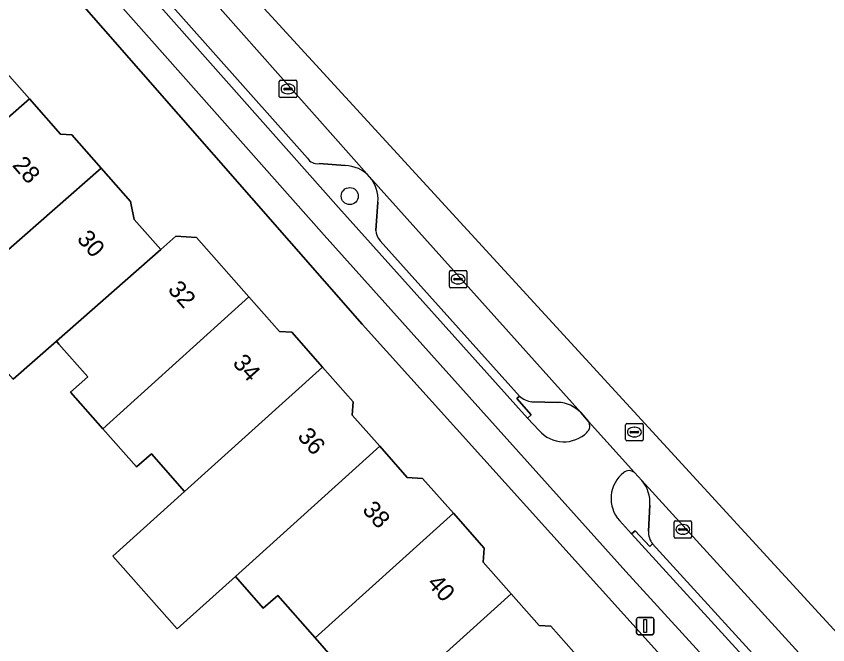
# Model space of a CAD drawing. Extents: x 159960 to 160866, y 382700 to 383354.
# Drawn here: x 160732.82 to 160779.46, y 383008.74 to 383044.85 of the extents above; entities that cross this region are included whole.
import ezdxf

# ---------------------------------------------------------------- set-up
doc = ezdxf.new("R2010")
doc.units = 0
for name, color, linetype in [('IMGEO_Berm_open', 7, 'Continuous'), ('IMGEO_Boom', 7, 'Continuous'), ('IMGEO_Erf', 7, 'Continuous'), ('IMGEO_Fietspad_gesloten', 7, 'Continuous'), ('IMGEO_Kolk', 7, 'Continuous'), ('IMGEO_Lichtmast', 7, 'Continuous'), ('IMGEO_Pand', 7, 'Continuous'), ('IMGEO_Pand_nummerreeks', 7, 'Continuous'), ('IMGEO_Parkeervlak_open', 7, 'Continuous'), ('IMGEO_Rijbaan_lokaal_gesloten', 7, 'Continuous'), ('IMGEO_Rioolput', 7, 'Continuous'), ('IMGEO_Verkeerseiland_gesloten', 7, 'Continuous'), ('IMGEO_Voetpad_open', 7, 'Continuous')]:
    doc.layers.add(name, color=color, linetype=linetype)

msp = doc.modelspace()

# ---------------------------------------------------------------- linework, layer by layer
at = {"layer": 'IMGEO_Berm_open'}
for points in [[(160700.875, 383094.511), (160700.804, 383094.591), (160698.59, 383096.925), (160695.704, 383099.8), (160694.16, 383101.338), (160689.088, 383106.239), (160687.38, 383107.889), (160684.6, 383110.794), (160683.967, 383110.175), (160686.696, 383107.388), (160688.818, 383104.989), (160694.352, 383098.361), (160701.018, 383090.565), (160751.341, 383033.866), (160762.195, 383021.758), (160762.421, 383021.957), (160761.588, 383022.894), (160761.747, 383023.027), (160753.731, 383031.938)], [(160749.55, 383036.695), (160733.605, 383054.628)], [(160751.719, 383036.276), (160750.222, 383036.377)], [(160753.486, 383032.54), (160753.608, 383034.161)], [(160777.531, 383005.612), (160769.389, 383014.532), (160769.234, 383014.393), (160768.396, 383015.285), (160768.171, 383015.103), (160799.663, 382980.632), (160799.88, 382980.845), (160798.069, 382982.871), (160798.218, 382983.015), (160781.941, 383000.79), (160781.708, 383001.508), (160781.754, 383002.991)]]:
    msp.add_lwpolyline(points, dxfattribs=at)
for centre, radius, start, end in [((160750.145, 383037.083), 0.71, 213.0951, 276.2565), ((160751.632, 383034.234), 2.044, 43.0411, 87.5688), ((160751.555, 383034.3), 2.058, 356.126, 40.228), ((160754.447, 383032.58), 0.962, 182.4046, 221.8858)]:
    msp.add_arc(centre, radius, start, end, dxfattribs=at)
at = {"layer": 'IMGEO_Boom'}
msp.add_circle((160751.985, 383034.517), 0.489, dxfattribs=at)
at = {"layer": 'IMGEO_Erf'}
for points in [[(160790.273, 382985.751), (160777.189, 383000), (160752.695, 383027.147), (160693.284, 383094.955), (160693.113, 383094.806), (160692.06, 383095.951)], [(160730.563, 383043.514), (160733.575, 383040.1), (160735.367, 383038.069), (160736.022, 383038.028), (160737.708, 383036.117), (160739.394, 383034.206), (160739.602, 383033.176), (160741.127, 383031.448), (160741.992, 383032.211), (160743.189, 383032.136), (160746.195, 383028.73), (160747.958, 383026.731), (160748.65, 383026.688), (160750.414, 383024.689), (160752.179, 383022.689), (160752.131, 383021.929), (160753.708, 383020.142), (160755.286, 383018.353), (160756.17, 383018.298), (160757.94, 383016.292), (160759.711, 383014.285), (160759.661, 383013.487), (160761.27, 383011.664), (160762.877, 383009.842), (160763.544, 383009.8), (160765.298, 383007.812)], [(160751.694, 383007.209), (160749.999, 383009.13), (160747.845, 383011.572), (160747.02, 383010.844), (160745.415, 383012.663), (160742.073, 383009.649), (160738.38, 383013.836), (160742.497, 383017.549), (160740.586, 383019.715), (160739.729, 383018.958), (160737.793, 383021.153), (160735.945, 383023.247), (160736.937, 383024.123), (160735.266, 383026.017), (160735.127, 383026.175), (160732.639, 383023.988)]]:
    msp.add_lwpolyline(points, dxfattribs=at)
at = {"layer": 'IMGEO_Fietspad_gesloten'}
for points in [[(160685.483, 383106.174), (160688.293, 383103.007), (160697.195, 383092.363), (160750.512, 383032.262), (160767.848, 383012.954), (160798.378, 382979.546), (160798.294, 382979.468), (160798.967, 382978.754), (160800.31, 382979.98), (160799.663, 382980.632), (160768.171, 383015.103), (160767.486, 383015.878)], [(160762.881, 383021.044), (160762.195, 383021.758), (160751.341, 383033.866), (160701.018, 383090.565)], [(160768.35, 383018.632), (160765.711, 383021.573)]]:
    msp.add_lwpolyline(points, dxfattribs=at)
for centre, radius, start, end in [((160765.264, 383021.312), 0.518, 313.186, 30.2271), ((160764.301, 383022.286), 1.887, 221.1807, 314.2582), ((160768.897, 383017.142), 1.894, 128.0222, 221.859), ((160768.039, 383018.256), 0.488, 50.4142, 129.2161)]:
    msp.add_arc(centre, radius, start, end, dxfattribs=at)
at = {"layer": 'IMGEO_Kolk'}
for p, q in [((160747.938, 383040.242), (160747.938, 383041.094)), ((160748.013, 383041.168), (160748.865, 383041.168)), ((160748.426, 383040.948), (160748.451, 383040.948)), ((160748.939, 383041.094), (160748.939, 383040.242)), ((160748.197, 383040.662), (160748.197, 383040.674)), ((160748.635, 383040.625), (160748.237, 383040.625)), ((160748.24, 383040.711), (160748.638, 383040.711)), ((160748.449, 383040.388), (160748.424, 383040.388)), ((160748.681, 383040.674), (160748.681, 383040.662)), ((160748.865, 383040.168), (160748.013, 383040.168)), ((160757.71, 383029.32), (160757.71, 383030.172)), ((160757.785, 383030.246), (160758.637, 383030.246)), ((160758.198, 383030.026), (160758.223, 383030.026)), ((160758.711, 383030.172), (160758.711, 383029.32)), ((160757.969, 383029.74), (160757.969, 383029.752)), ((160758.407, 383029.703), (160758.009, 383029.703)), ((160758.012, 383029.789), (160758.41, 383029.789)), ((160758.453, 383029.752), (160758.453, 383029.74)), ((160758.637, 383029.246), (160757.785, 383029.246)), ((160758.221, 383029.466), (160758.196, 383029.466)), ((160770.63, 383014.94), (160770.63, 383015.792)), ((160770.705, 383015.866), (160771.557, 383015.866)), ((160771.118, 383015.646), (160771.143, 383015.646)), ((160771.631, 383015.792), (160771.631, 383014.94)), ((160770.889, 383015.36), (160770.889, 383015.372)), ((160771.327, 383015.323), (160770.929, 383015.323)), ((160770.932, 383015.409), (160771.33, 383015.409)), ((160771.373, 383015.372), (160771.373, 383015.36)), ((160771.557, 383014.866), (160770.705, 383014.866)), ((160771.141, 383015.086), (160771.116, 383015.086))]:
    msp.add_line(p, q, dxfattribs=at)
for points in [[(160747.938, 383040.242), (160747.938, 383041.094)], [(160748.013, 383041.168), (160748.865, 383041.168)], [(160748.939, 383041.094), (160748.939, 383040.242)], [(160748.865, 383040.168), (160748.013, 383040.168)], [(160757.71, 383029.32), (160757.71, 383030.172)], [(160757.785, 383030.246), (160758.637, 383030.246)], [(160758.711, 383030.172), (160758.711, 383029.32)], [(160758.637, 383029.246), (160757.785, 383029.246)], [(160770.63, 383014.94), (160770.63, 383015.792)], [(160770.705, 383015.866), (160771.557, 383015.866)], [(160771.631, 383015.792), (160771.631, 383014.94)], [(160771.557, 383014.866), (160770.705, 383014.866)]]:
    msp.add_lwpolyline(points, dxfattribs=at)
for centre, radius, start, end in [((160748.015, 383041.092), 0.0765, 91.552, 178.448), ((160748.015, 383041.092), 0.0765, 91.552, 178.448), ((160748.863, 383041.092), 0.0765, 1.552, 88.448), ((160748.863, 383041.092), 0.0765, 1.552, 88.448), ((160748.237, 383040.671), 0.0403, 85.8775, 175.7526), ((160748.234, 383040.661), 0.0366, 178.938, 274.7102), ((160748.638, 383040.668), 0.043, 264.8664, 352.4533), ((160748.642, 383040.673), 0.0386, 1.7309, 96.639), ((160748.015, 383040.244), 0.0765, 181.552, 268.448), ((160748.015, 383040.244), 0.0765, 181.552, 268.448), ((160748.863, 383040.244), 0.0765, 271.552, 358.448), ((160748.863, 383040.244), 0.0765, 271.552, 358.448), ((160757.787, 383030.17), 0.0765, 91.552, 178.448), ((160757.787, 383030.17), 0.0765, 91.552, 178.448), ((160758.635, 383030.17), 0.0765, 1.552, 88.448), ((160758.635, 383030.17), 0.0765, 1.552, 88.448), ((160758.009, 383029.749), 0.0403, 85.8775, 175.7526), ((160758.006, 383029.739), 0.0366, 178.938, 274.7102), ((160758.41, 383029.746), 0.043, 264.8664, 352.4533), ((160758.414, 383029.751), 0.0386, 1.7309, 96.639), ((160757.787, 383029.322), 0.0765, 181.552, 268.448), ((160757.787, 383029.322), 0.0765, 181.552, 268.448), ((160758.635, 383029.322), 0.0765, 271.552, 358.448), ((160758.635, 383029.322), 0.0765, 271.552, 358.448), ((160770.707, 383015.79), 0.0765, 91.552, 178.448), ((160770.707, 383015.79), 0.0765, 91.552, 178.448), ((160771.555, 383015.79), 0.0765, 1.552, 88.448), ((160771.555, 383015.79), 0.0765, 1.552, 88.448), ((160770.929, 383015.369), 0.0403, 85.8775, 175.7526), ((160770.926, 383015.359), 0.0366, 178.938, 274.7102), ((160771.33, 383015.366), 0.043, 264.8664, 352.4533), ((160771.334, 383015.371), 0.0386, 1.7309, 96.639), ((160770.707, 383014.942), 0.0765, 181.552, 268.448), ((160770.707, 383014.942), 0.0765, 181.552, 268.448), ((160771.555, 383014.942), 0.0765, 271.552, 358.448), ((160771.555, 383014.942), 0.0765, 271.552, 358.448)]:
    msp.add_arc(centre, radius, start, end, dxfattribs=at)
for centre, major_axis, ratio, start_param, end_param in [((160748.425, 383040.668), (-0.387, 0.002), 0.722429, 4.712389, 7.853982), ((160748.45, 383040.668), (-0.39, 0.002), 0.717154, 1.570796, 4.712389), ((160758.197, 383029.746), (-0.387, 0.002), 0.722429, 4.712389, 7.853982), ((160758.222, 383029.746), (-0.39, 0.002), 0.717154, 1.570796, 4.712389), ((160771.117, 383015.366), (-0.387, 0.002), 0.722429, 4.712389, 7.853982), ((160771.142, 383015.366), (-0.39, 0.002), 0.717154, 1.570796, 4.712389)]:
    msp.add_ellipse(centre, major_axis=major_axis, ratio=ratio, start_param=start_param, end_param=end_param, dxfattribs=at)
at = {"layer": 'IMGEO_Lichtmast'}
for p, q in [((160768.472, 383009.415), (160768.472, 383010.215)), ((160768.472, 383010.215), (160768.472, 383009.415)), ((160768.572, 383010.315), (160769.362, 383010.315)), ((160769.362, 383010.315), (160768.572, 383010.315)), ((160769.462, 383010.215), (160769.462, 383009.415)), ((160769.462, 383009.415), (160769.462, 383010.215)), ((160769.362, 383009.315), (160768.572, 383009.315)), ((160768.572, 383009.315), (160769.362, 383009.315))]:
    msp.add_line(p, q, dxfattribs=at)
msp.add_lwpolyline([(160768.892, 383010.19), (160769.042, 383010.19), (160769.042, 383009.44), (160768.892, 383009.44), (160768.892, 383010.19)], dxfattribs=at)
for centre, start, end in [((160768.572, 383010.215), 90, 180), ((160768.572, 383010.215), 90, 180), ((160769.362, 383010.215), 0, 90), ((160769.362, 383010.215), 360, 90), ((160768.572, 383009.415), 180, 270), ((160768.572, 383009.415), 180, 270), ((160769.362, 383009.415), 270, 0), ((160769.362, 383009.415), 270, 0)]:
    msp.add_arc(centre, 0.1, start, end, dxfattribs=at)
at = {"layer": 'IMGEO_Pand'}
for points in [[(160733.575, 383040.1), (160730.563, 383043.514), (160729.341, 383043.59), (160728.806, 383043.118), (160721.3, 383036.501), (160723.12, 383034.436), (160724.855, 383032.468)], [(160724.855, 383032.468), (160725.14, 383032.145), (160725.272, 383032.262), (160726.92, 383030.394), (160727.838, 383031.205), (160729.693, 383029.102), (160737.708, 383036.117), (160736.022, 383038.028), (160735.367, 383038.069), (160733.575, 383040.1)], [(160741.127, 383031.448), (160739.602, 383033.176), (160739.394, 383034.206), (160737.708, 383036.117), (160729.693, 383029.102), (160731.632, 383026.904), (160730.751, 383026.127), (160732.639, 383023.988), (160735.127, 383026.175)], [(160746.195, 383028.73), (160743.189, 383032.136), (160741.992, 383032.211), (160741.127, 383031.448), (160735.127, 383026.175), (160735.266, 383026.017), (160736.937, 383024.123), (160735.945, 383023.247), (160737.793, 383021.153)], [(160750.414, 383024.689), (160748.65, 383026.688), (160747.958, 383026.731), (160746.195, 383028.73), (160737.793, 383021.153), (160739.729, 383018.958), (160740.586, 383019.715), (160742.497, 383017.549)], [(160750.414, 383024.689), (160742.497, 383017.549), (160738.38, 383013.836), (160742.073, 383009.649), (160745.415, 383012.663), (160753.708, 383020.142), (160752.131, 383021.929), (160752.179, 383022.689)], [(160749.999, 383009.13), (160757.94, 383016.292), (160756.17, 383018.298), (160755.286, 383018.353), (160753.708, 383020.142), (160745.415, 383012.663), (160747.02, 383010.844), (160747.845, 383011.572)], [(160761.27, 383011.664), (160759.661, 383013.487), (160759.711, 383014.285), (160757.94, 383016.292), (160749.999, 383009.13), (160751.694, 383007.209), (160750.76, 383006.385), (160752.823, 383004.046)], [(160761.27, 383011.664), (160752.823, 383004.046), (160754.488, 383002.159), (160755.371, 383002.937), (160757.384, 383000.676), (160765.298, 383007.812), (160763.544, 383009.8), (160762.877, 383009.842)]]:
    msp.add_lwpolyline(points, close=True, dxfattribs=at)
at = {"layer": 'IMGEO_Parkeervlak_open'}
for points in [[(160753.126, 383035.629), (160733.109, 383058.204)], [(160733.605, 383054.628), (160749.55, 383036.695)], [(160750.222, 383036.377), (160751.719, 383036.276)], [(160765.265, 383022.079), (160753.126, 383035.629)], [(160753.608, 383034.161), (160753.486, 383032.54)], [(160753.731, 383031.938), (160761.747, 383023.027)], [(160762.446, 383022.686), (160763.954, 383022.663)], [(160781.34, 383004.391), (160768.775, 383018.171)], [(160769.234, 383016.761), (160769.147, 383015.273)], [(160769.389, 383014.532), (160777.531, 383005.612)]]:
    msp.add_lwpolyline(points, dxfattribs=at)
for centre, radius, start, end in [((160750.145, 383037.083), 0.71, 213.0951, 276.2565), ((160751.632, 383034.234), 2.044, 43.0411, 87.5688), ((160751.555, 383034.3), 2.058, 356.126, 40.228), ((160754.447, 383032.58), 0.962, 182.4046, 221.8858), ((160762.738, 383024.172), 1.515, 229.1217, 258.8684), ((160763.884, 383020.742), 1.922, 44.0636, 87.9141), ((160767.33, 383016.921), 1.91, 355.1954, 40.8681), ((160770.343, 383015.253), 1.196, 179.0641, 217.1085)]:
    msp.add_arc(centre, radius, start, end, dxfattribs=at)
at = {"layer": 'IMGEO_Rijbaan_lokaal_gesloten'}
msp.add_lwpolyline([(160856.414, 382930.084), (160844.823, 382938.754), (160792.96, 382995.267), (160690.092, 383107.358), (160689.088, 383106.239), (160694.16, 383101.338), (160695.704, 383099.8), (160698.59, 383096.925), (160700.804, 383094.591), (160700.875, 383094.511), (160712.709, 383081.187), (160712.997, 383080.863), (160713.176, 383080.662), (160719.676, 383073.343), (160732.702, 383058.662), (160732.84, 383058.507), (160733.109, 383058.204), (160753.126, 383035.629), (160765.265, 383022.079), (160765.711, 383021.573), (160768.35, 383018.632), (160768.775, 383018.171), (160781.34, 383004.391), (160801.711, 382982.115)], dxfattribs=at)
at = {"layer": 'IMGEO_Rioolput'}
for p, q in [((160767.844, 383020.531), (160767.844, 383021.383)), ((160767.919, 383021.457), (160768.771, 383021.457)), ((160768.332, 383021.237), (160768.357, 383021.237)), ((160768.845, 383021.383), (160768.845, 383020.531)), ((160768.103, 383020.951), (160768.103, 383020.963)), ((160768.541, 383020.914), (160768.143, 383020.914)), ((160768.146, 383021), (160768.544, 383021)), ((160768.587, 383020.963), (160768.587, 383020.951)), ((160768.771, 383020.457), (160767.919, 383020.457)), ((160768.355, 383020.677), (160768.33, 383020.677))]:
    msp.add_line(p, q, dxfattribs=at)
for points in [[(160767.844, 383020.531), (160767.844, 383021.383)], [(160767.919, 383021.457), (160768.771, 383021.457)], [(160768.845, 383021.383), (160768.845, 383020.531)], [(160768.771, 383020.457), (160767.919, 383020.457)]]:
    msp.add_lwpolyline(points, dxfattribs=at)
for centre, radius, start, end in [((160767.921, 383021.381), 0.0765, 91.552, 178.448), ((160767.921, 383021.381), 0.0765, 91.552, 178.448), ((160768.769, 383021.381), 0.0765, 1.552, 88.448), ((160768.769, 383021.381), 0.0765, 1.552, 88.448), ((160768.143, 383020.96), 0.0403, 85.8775, 175.7526), ((160768.14, 383020.95), 0.0366, 178.938, 274.7102), ((160768.544, 383020.957), 0.043, 264.8664, 352.4533), ((160768.548, 383020.962), 0.0386, 1.7309, 96.639), ((160767.921, 383020.533), 0.0765, 181.552, 268.448), ((160767.921, 383020.533), 0.0765, 181.552, 268.448), ((160768.769, 383020.533), 0.0765, 271.552, 358.448), ((160768.769, 383020.533), 0.0765, 271.552, 358.448)]:
    msp.add_arc(centre, radius, start, end, dxfattribs=at)
for centre, major_axis, ratio, start_param, end_param in [((160768.331, 383020.957), (-0.387, 0.002), 0.722429, 4.712389, 7.853982), ((160768.356, 383020.957), (-0.39, 0.002), 0.717154, 1.570796, 4.712389)]:
    msp.add_ellipse(centre, major_axis=major_axis, ratio=ratio, start_param=start_param, end_param=end_param, dxfattribs=at)
at = {"layer": 'IMGEO_Verkeerseiland_gesloten'}
for points in [[(160761.747, 383023.027), (160761.588, 383022.894), (160762.421, 383021.957), (160762.195, 383021.758), (160762.881, 383021.044)], [(160763.954, 383022.663), (160762.446, 383022.686)], [(160765.711, 383021.573), (160765.265, 383022.079)], [(160768.775, 383018.171), (160768.35, 383018.632)], [(160769.147, 383015.273), (160769.234, 383016.761)], [(160767.486, 383015.878), (160768.171, 383015.103), (160768.396, 383015.285), (160769.234, 383014.393), (160769.389, 383014.532)]]:
    msp.add_lwpolyline(points, dxfattribs=at)
for centre, radius, start, end in [((160762.738, 383024.172), 1.515, 229.1217, 258.8684), ((160763.884, 383020.742), 1.922, 44.0636, 87.9141), ((160765.264, 383021.312), 0.518, 313.186, 30.2271), ((160764.301, 383022.286), 1.887, 221.1807, 314.2582), ((160768.897, 383017.142), 1.894, 128.0222, 221.859), ((160768.039, 383018.256), 0.488, 50.4142, 129.2161), ((160767.33, 383016.921), 1.91, 355.1954, 40.8681), ((160770.343, 383015.253), 1.196, 179.0641, 217.1085)]:
    msp.add_arc(centre, radius, start, end, dxfattribs=at)
at = {"layer": 'IMGEO_Voetpad_open'}
for points in [[(160680.196, 383109.392), (160682.942, 383106.472), (160690.078, 383098.106), (160692.06, 383095.951), (160693.113, 383094.806), (160693.284, 383094.955), (160752.695, 383027.147), (160777.189, 383000), (160790.273, 382985.751), (160790.193, 382984.786), (160790.89, 382984.564), (160791.864, 382984.255), (160795.23, 382980.568), (160804.564, 382970.344), (160805.227, 382969.703), (160808.476, 382966.141), (160814.655, 382959.316)], [(160813.794, 382962.524), (160806.085, 382971.014), (160805.536, 382970.523), (160800.113, 382976.385), (160800.674, 382976.938), (160798.967, 382978.754), (160798.294, 382979.468), (160798.378, 382979.546), (160767.848, 383012.954), (160750.512, 383032.262), (160697.195, 383092.363), (160688.293, 383103.007)]]:
    msp.add_lwpolyline(points, dxfattribs=at)

# ---------------------------------------------------------------- texts
at = {"layer": 'IMGEO_Pand_nummerreeks'}
for s, rotation, p in [('28', 311.2139, (160732.549, 383036.264)), ('30', 311.2126, (160736.261, 383032.024)), ('32', 311.4533, (160741.484, 383029.113)), ('34', 311.4512, (160745.211, 383024.894)), ('36', 311.4512, (160748.935, 383020.677)), ('38', 311.4512, (160752.662, 383016.457)), ('40', 311.4512, (160756.387, 383012.239))]:
    msp.add_text(s, height=1, rotation=rotation, dxfattribs=at).set_placement(p)

doc.saveas('drawing.dxf')
